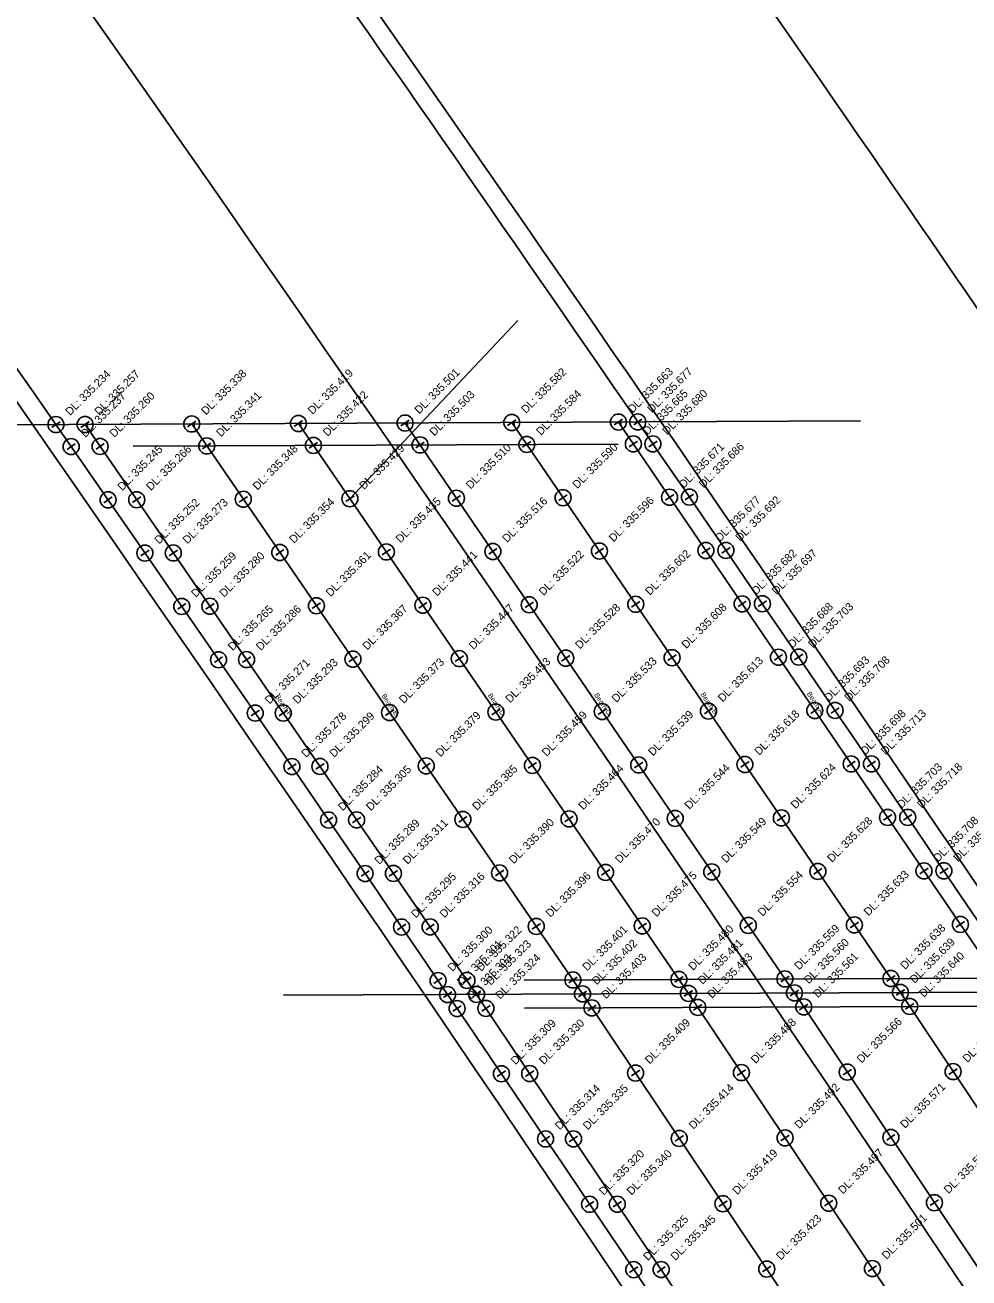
# Model space of a CAD drawing. Extents: x 1524497 to 1524592, y 1103688 to 1103812.
# Drawn here: x 1524518.53 to 1524542.12, y 1103749.84 to 1103781.14 of the extents above; entities that cross this region are included whole.
import ezdxf

# ---------------------------------------------------------------- set-up
doc = ezdxf.new("R2010")
doc.units = 0
doc.layers.add('Level 1', color=7, linetype='Continuous')

msp = doc.modelspace()

# ---------------------------------------------------------------- linework, layer by layer
at = {"layer": 'Level 1'}
for p, q in [((1524526.65, 1103769.309), (1524530.852, 1103773.763)), ((1524539.408, 1103771.253), (1524515.175, 1103771.141)), ((1524519.407, 1103771.231), (1524519.202, 1103771.089)), ((1524519.929, 1103771.092), (1524520.135, 1103771.234)), ((1524520.032, 1103771.163), (1524529.816, 1103756.923)), ((1524522.595, 1103771.105), (1524522.801, 1103771.246)), ((1524522.698, 1103771.176), (1524532.464, 1103756.935)), ((1524525.261, 1103771.117), (1524525.467, 1103771.259)), ((1524525.364, 1103771.188), (1524535.113, 1103756.948)), ((1524527.927, 1103771.13), (1524528.133, 1103771.271)), ((1524528.03, 1103771.2), (1524537.761, 1103756.96)), ((1524530.593, 1103771.142), (1524530.799, 1103771.283)), ((1524530.696, 1103771.213), (1524540.409, 1103756.972)), ((1524533.259, 1103771.155), (1524533.465, 1103771.295)), ((1524533.362, 1103771.225), (1524543.057, 1103756.984)), ((1524533.949, 1103771.298), (1524533.743, 1103771.156)), ((1524519.788, 1103770.683), (1524519.582, 1103770.54)), ((1524520.306, 1103770.544), (1524520.512, 1103770.686)), ((1524533.352, 1103770.675), (1524521.236, 1103770.619)), ((1524522.971, 1103770.557), (1524523.177, 1103770.698)), ((1524525.636, 1103770.569), (1524525.843, 1103770.71)), ((1524528.302, 1103770.581), (1524528.508, 1103770.723)), ((1524530.967, 1103770.594), (1524531.173, 1103770.735)), ((1524533.632, 1103770.606), (1524533.839, 1103770.747)), ((1524534.326, 1103770.75), (1524534.12, 1103770.608)), ((1524520.71, 1103769.352), (1524520.505, 1103769.21)), ((1524521.22, 1103769.214), (1524521.426, 1103769.355)), ((1524523.884, 1103769.226), (1524524.09, 1103769.368)), ((1524526.547, 1103769.239), (1524526.754, 1103769.38)), ((1524529.211, 1103769.251), (1524529.417, 1103769.392)), ((1524531.874, 1103769.263), (1524532.081, 1103769.404)), ((1524534.538, 1103769.276), (1524534.744, 1103769.416)), ((1524535.239, 1103769.419), (1524535.033, 1103769.278)), ((1524521.632, 1103768.021), (1524521.426, 1103767.879)), ((1524522.135, 1103767.882), (1524522.341, 1103768.024)), ((1524524.797, 1103767.895), (1524525.003, 1103768.036)), ((1524527.459, 1103767.907), (1524527.665, 1103768.048)), ((1524530.12, 1103767.92), (1524530.327, 1103768.061)), ((1524532.782, 1103767.932), (1524532.989, 1103768.073)), ((1524535.444, 1103767.944), (1524535.651, 1103768.085)), ((1524536.152, 1103768.088), (1524535.945, 1103767.946)), ((1524523.05, 1103766.55), (1524523.256, 1103766.692)), ((1524525.71, 1103766.563), (1524525.917, 1103766.704)), ((1524528.371, 1103766.575), (1524528.577, 1103766.716)), ((1524531.031, 1103766.587), (1524531.237, 1103766.728)), ((1524533.691, 1103766.6), (1524533.897, 1103766.741)), ((1524536.351, 1103766.612), (1524536.558, 1103766.753)), ((1524537.063, 1103766.755), (1524536.856, 1103766.614)), ((1524522.552, 1103766.689), (1524522.347, 1103766.547)), ((1524523.471, 1103765.356), (1524523.265, 1103765.214)), ((1524523.966, 1103765.217), (1524524.172, 1103765.359)), ((1524526.625, 1103765.23), (1524526.831, 1103765.371)), ((1524529.283, 1103765.242), (1524529.489, 1103765.383)), ((1524531.942, 1103765.254), (1524532.148, 1103765.395)), ((1524534.6, 1103765.267), (1524534.807, 1103765.408)), ((1524537.259, 1103765.279), (1524537.465, 1103765.42)), ((1524537.973, 1103765.422), (1524537.766, 1103765.281)), ((1524524.389, 1103764.022), (1524524.183, 1103763.88)), ((1524524.883, 1103763.883), (1524525.089, 1103764.025)), ((1524527.539, 1103763.896), (1524527.746, 1103764.037)), ((1524530.196, 1103763.908), (1524530.403, 1103764.049)), ((1524532.853, 1103763.92), (1524533.06, 1103764.061)), ((1524535.51, 1103763.933), (1524535.716, 1103764.074)), ((1524538.167, 1103763.945), (1524538.373, 1103764.086)), ((1524538.881, 1103764.088), (1524538.675, 1103763.948)), ((1524525.306, 1103762.687), (1524525.099, 1103762.545)), ((1524525.8, 1103762.549), (1524526.006, 1103762.69)), ((1524528.455, 1103762.561), (1524528.661, 1103762.702)), ((1524531.11, 1103762.573), (1524531.316, 1103762.715)), ((1524533.765, 1103762.586), (1524533.972, 1103762.727)), ((1524536.42, 1103762.598), (1524536.627, 1103762.739)), ((1524539.075, 1103762.61), (1524539.282, 1103762.751)), ((1524539.789, 1103762.753), (1524539.582, 1103762.613)), ((1524532.024, 1103761.238), (1524532.231, 1103761.379)), ((1524534.678, 1103761.25), (1524534.884, 1103761.391)), ((1524537.331, 1103761.262), (1524537.538, 1103761.403)), ((1524539.985, 1103761.275), (1524540.191, 1103761.415)), ((1524540.695, 1103761.418), (1524540.488, 1103761.277)), ((1524526.221, 1103761.351), (1524526.015, 1103761.21)), ((1524526.717, 1103761.213), (1524526.923, 1103761.355)), ((1524529.371, 1103761.225), (1524529.577, 1103761.367)), ((1524527.135, 1103760.015), (1524526.929, 1103759.874)), ((1524527.636, 1103759.877), (1524527.842, 1103760.018)), ((1524530.287, 1103759.889), (1524530.494, 1103760.03)), ((1524532.939, 1103759.901), (1524533.145, 1103760.043)), ((1524535.591, 1103759.914), (1524535.797, 1103760.055)), ((1524538.243, 1103759.926), (1524538.449, 1103760.067)), ((1524540.894, 1103759.938), (1524541.101, 1103760.079)), ((1524541.6, 1103760.081), (1524541.393, 1103759.941)), ((1524528.048, 1103758.677), (1524527.841, 1103758.536)), ((1524528.554, 1103758.539), (1524528.76, 1103758.681)), ((1524531.204, 1103758.552), (1524531.411, 1103758.693)), ((1524533.855, 1103758.564), (1524534.061, 1103758.705)), ((1524536.505, 1103758.576), (1524536.711, 1103758.717)), ((1524539.155, 1103758.589), (1524539.361, 1103758.73)), ((1524541.805, 1103758.601), (1524542.011, 1103758.742)), ((1524528.959, 1103757.339), (1524528.752, 1103757.198)), ((1524529.474, 1103757.201), (1524529.68, 1103757.343)), ((1524543.043, 1103757.334), (1524531.008, 1103757.279)), ((1524532.122, 1103757.214), (1524532.328, 1103757.355)), ((1524534.771, 1103757.226), (1524534.977, 1103757.367)), ((1524537.419, 1103757.238), (1524537.625, 1103757.379)), ((1524540.067, 1103757.251), (1524540.274, 1103757.392)), ((1524549.062, 1103757.012), (1524524.992, 1103756.901)), ((1524529.197, 1103756.99), (1524528.99, 1103756.85)), ((1524529.197, 1103756.99), (1524528.99, 1103756.85)), ((1524529.713, 1103756.852), (1524529.919, 1103756.994)), ((1524529.713, 1103756.854), (1524529.92, 1103756.993)), ((1524532.361, 1103756.865), (1524532.568, 1103757.006)), ((1524532.361, 1103756.866), (1524532.568, 1103757.005)), ((1524535.009, 1103756.877), (1524535.216, 1103757.018)), ((1524535.009, 1103756.878), (1524535.216, 1103757.017)), ((1524537.657, 1103756.889), (1524537.864, 1103757.03)), ((1524537.657, 1103756.891), (1524537.865, 1103757.029)), ((1524540.305, 1103756.902), (1524540.512, 1103757.043)), ((1524540.305, 1103756.903), (1524540.513, 1103757.041)), ((1524529.816, 1103756.923), (1524541.257, 1103739.876)), ((1524532.464, 1103756.935), (1524543.885, 1103739.888)), ((1524535.113, 1103756.948), (1524546.512, 1103739.9)), ((1524537.761, 1103756.96), (1524549.14, 1103739.912)), ((1524537.889, 1103756.542), (1524538.097, 1103756.68)), ((1524540.409, 1103756.972), (1524551.767, 1103739.924)), ((1524540.537, 1103756.554), (1524540.745, 1103756.693)), ((1524529.434, 1103756.641), (1524529.227, 1103756.501)), ((1524529.947, 1103756.505), (1524530.154, 1103756.644)), ((1524543.047, 1103756.634), (1524531.012, 1103756.579)), ((1524532.594, 1103756.517), (1524532.802, 1103756.656)), ((1524535.242, 1103756.529), (1524535.45, 1103756.668)), ((1524530.54, 1103755.012), (1524530.333, 1103754.871)), ((1524531.04, 1103754.875), (1524531.248, 1103755.014)), ((1524533.686, 1103754.887), (1524533.894, 1103755.027)), ((1524536.332, 1103754.9), (1524536.539, 1103755.039)), ((1524538.977, 1103754.912), (1524539.185, 1103755.051)), ((1524541.623, 1103754.924), (1524541.831, 1103755.063)), ((1524531.644, 1103753.381), (1524531.437, 1103753.241)), ((1524532.135, 1103753.244), (1524532.342, 1103753.384)), ((1524534.778, 1103753.257), (1524534.986, 1103753.396)), ((1524537.422, 1103753.269), (1524537.63, 1103753.408)), ((1524540.066, 1103753.281), (1524540.273, 1103753.42)), ((1524532.747, 1103751.749), (1524532.54, 1103751.609)), ((1524533.23, 1103751.613), (1524533.438, 1103751.752)), ((1524535.872, 1103751.625), (1524536.079, 1103751.764)), ((1524538.513, 1103751.637), (1524538.721, 1103751.776)), ((1524541.155, 1103751.649), (1524541.363, 1103751.788)), ((1524533.848, 1103750.116), (1524533.64, 1103749.976)), ((1524534.326, 1103749.979), (1524534.534, 1103750.119)), ((1524536.966, 1103749.992), (1524537.173, 1103750.131)), ((1524539.605, 1103750.004), (1524539.813, 1103750.143))]:
    msp.add_line(p, q, dxfattribs=at)
for points in [[(1524520.094, 1103771.074), (1524520.084, 1103771.199), (1524520.032, 1103771.163)], [(1524522.76, 1103771.086), (1524522.75, 1103771.211), (1524522.698, 1103771.176)], [(1524525.425, 1103771.099), (1524525.416, 1103771.223), (1524525.364, 1103771.188)], [(1524528.091, 1103771.111), (1524528.082, 1103771.236), (1524528.03, 1103771.2)], [(1524530.757, 1103771.123), (1524530.748, 1103771.248), (1524530.696, 1103771.213)], [(1524533.423, 1103771.135), (1524533.414, 1103771.26), (1524533.362, 1103771.225)], [(1524537.821, 1103756.87), (1524537.813, 1103756.995), (1524537.761, 1103756.96)], [(1524540.469, 1103756.882), (1524540.461, 1103757.007), (1524540.409, 1103756.972)], [(1524529.877, 1103756.833), (1524529.868, 1103756.958), (1524529.816, 1103756.923)], [(1524532.525, 1103756.846), (1524532.516, 1103756.97), (1524532.464, 1103756.935)], [(1524535.173, 1103756.858), (1524535.164, 1103756.982), (1524535.113, 1103756.948)]]:
    msp.add_lwpolyline(points, dxfattribs=at)
for centre in [(1524525.364, 1103771.188), (1524528.03, 1103771.2), (1524530.696, 1103771.213), (1524533.362, 1103771.225), (1524533.846, 1103771.227), (1524519.304, 1103771.16), (1524520.032, 1103771.163), (1524522.698, 1103771.176), (1524519.685, 1103770.612), (1524520.409, 1103770.615), (1524523.074, 1103770.627), (1524525.74, 1103770.64), (1524528.405, 1103770.652), (1524531.07, 1103770.664), (1524533.735, 1103770.677), (1524534.223, 1103770.679), (1524526.65, 1103769.309), (1524529.314, 1103769.321), (1524531.978, 1103769.334), (1524534.641, 1103769.346), (1524535.136, 1103769.348), (1524520.608, 1103769.281), (1524521.323, 1103769.284), (1524523.987, 1103769.297), (1524521.529, 1103767.95), (1524522.238, 1103767.953), (1524524.9, 1103767.965), (1524527.562, 1103767.978), (1524530.224, 1103767.99), (1524532.886, 1103768.002), (1524535.547, 1103768.015), (1524536.049, 1103768.017), (1524522.449, 1103766.618), (1524523.153, 1103766.621), (1524525.814, 1103766.633), (1524528.474, 1103766.646), (1524531.134, 1103766.658), (1524533.794, 1103766.67), (1524536.454, 1103766.682), (1524536.96, 1103766.685), (1524523.368, 1103765.285), (1524524.069, 1103765.288), (1524526.728, 1103765.3), (1524529.386, 1103765.313), (1524532.045, 1103765.325), (1524534.703, 1103765.337), (1524537.362, 1103765.349), (1524537.869, 1103765.352), (1524532.956, 1103763.991), (1524535.613, 1103764.003), (1524538.27, 1103764.016), (1524538.778, 1103764.018), (1524524.286, 1103763.951), (1524524.986, 1103763.954), (1524527.643, 1103763.966), (1524530.299, 1103763.979), (1524525.203, 1103762.616), (1524525.903, 1103762.619), (1524528.558, 1103762.632), (1524531.213, 1103762.644), (1524533.868, 1103762.656), (1524536.523, 1103762.668), (1524539.179, 1103762.681), (1524539.685, 1103762.683), (1524526.118, 1103761.281), (1524526.82, 1103761.284), (1524529.474, 1103761.296), (1524532.127, 1103761.308), (1524534.781, 1103761.321), (1524537.434, 1103761.333), (1524540.088, 1103761.345), (1524540.591, 1103761.347), (1524527.032, 1103759.944), (1524527.739, 1103759.947), (1524530.39, 1103759.96), (1524533.042, 1103759.972), (1524535.694, 1103759.984), (1524538.346, 1103759.996), (1524540.998, 1103760.009), (1524541.496, 1103760.011), (1524541.908, 1103758.671), (1524527.944, 1103758.607), (1524528.657, 1103758.61), (1524531.308, 1103758.622), (1524533.958, 1103758.635), (1524536.608, 1103758.647), (1524539.258, 1103758.659), (1524528.856, 1103757.269), (1524529.577, 1103757.272), (1524532.225, 1103757.284), (1524534.874, 1103757.297), (1524537.522, 1103757.309), (1524540.171, 1103757.321), (1524529.093, 1103756.92), (1524529.093, 1103756.92), (1524529.816, 1103756.923), (1524529.816, 1103756.923), (1524532.464, 1103756.935), (1524532.464, 1103756.935), (1524535.113, 1103756.948), (1524535.113, 1103756.948), (1524537.761, 1103756.96), (1524537.761, 1103756.96), (1524540.409, 1103756.972), (1524540.409, 1103756.972), (1524529.33, 1103756.571), (1524530.051, 1103756.574), (1524532.698, 1103756.587), (1524535.346, 1103756.599), (1524537.993, 1103756.611), (1524540.641, 1103756.623), (1524530.437, 1103754.942), (1524531.144, 1103754.945), (1524533.79, 1103754.957), (1524536.435, 1103754.969), (1524539.081, 1103754.982), (1524541.727, 1103754.994), (1524540.17, 1103753.351), (1524531.541, 1103753.311), (1524532.239, 1103753.314), (1524534.882, 1103753.326), (1524537.526, 1103753.339), (1524532.643, 1103751.679), (1524533.334, 1103751.682), (1524535.975, 1103751.694), (1524538.617, 1103751.707), (1524541.259, 1103751.719), (1524533.744, 1103750.046), (1524534.43, 1103750.049), (1524537.069, 1103750.061), (1524539.709, 1103750.073)]:
    msp.add_circle(centre, 0.2, dxfattribs=at)
for radius in [1750, 1750, 1750, 1750, 1750, 1750, 1750, 1750, 1741.4, 1741.4, 1741.4, 1741.4, 1741.4, 1741.4, 1741.4, 1741.4, 1741.88, 1741.88, 1741.88, 1741.88, 1741.88, 1741.88, 1741.88, 1741.88, 1736, 1736, 1736, 1736, 1736, 1736, 1736, 1736, 1729.4, 1729.4, 1729.4, 1729.4, 1729.4, 1729.4, 1729.4, 1729.4, 1728.92, 1728.92, 1728.92, 1728.92, 1728.92, 1728.92, 1728.92, 1728.92]:
    msp.add_arc((1523099.068, 1102784.371), radius, 33.735131, 35.977852, dxfattribs=at)

# ---------------------------------------------------------------- texts
for s, height, rotation, p in [('DL: 335.234', 0.2, 45, (1524519.658, 1103771.372)), ('DL: 335.257', 0.2, 45, (1524520.386, 1103771.375)), ('DL: 335.338', 0.2, 45, (1524523.052, 1103771.388)), ('DL: 335.419', 0.2, 45, (1524525.718, 1103771.4)), ('DL: 335.501', 0.2, 45, (1524528.384, 1103771.412)), ('DL: 335.582', 0.2, 45, (1524531.05, 1103771.425)), ('DL: 335.663', 0.2, 45, (1524533.716, 1103771.437)), ('DL: 335.677', 0.2, 45, (1524534.2, 1103771.439)), ('DL: 335.584', 0.2, 45, (1524531.424, 1103770.876)), ('DL: 335.665', 0.2, 45, (1524534.089, 1103770.889)), ('DL: 335.680', 0.2, 45, (1524534.576, 1103770.891)), ('DL: 335.237', 0.2, 45, (1524520.039, 1103770.824)), ('DL: 335.260', 0.2, 45, (1524520.763, 1103770.827)), ('DL: 335.341', 0.2, 45, (1524523.428, 1103770.839)), ('DL: 335.422', 0.2, 45, (1524526.093, 1103770.852)), ('DL: 335.503', 0.2, 45, (1524528.758, 1103770.864)), ('DL: 335.245', 0.2, 45, (1524520.961, 1103769.493)), ('DL: 335.266', 0.2, 45, (1524521.677, 1103769.497)), ('DL: 335.348', 0.2, 45, (1524524.34, 1103769.509)), ('DL: 335.429', 0.2, 45, (1524527.004, 1103769.521)), ('DL: 335.510', 0.2, 45, (1524529.668, 1103769.534)), ('DL: 335.590', 0.2, 45, (1524532.331, 1103769.546)), ('DL: 335.671', 0.2, 45, (1524534.995, 1103769.558)), ('DL: 335.686', 0.2, 45, (1524535.49, 1103769.561)), ('DL: 335.252', 0.2, 45, (1524521.883, 1103768.162)), ('DL: 335.273', 0.2, 45, (1524522.592, 1103768.165)), ('DL: 335.354', 0.2, 45, (1524525.253, 1103768.178)), ('DL: 335.435', 0.2, 45, (1524527.915, 1103768.19)), ('DL: 335.516', 0.2, 45, (1524530.577, 1103768.202)), ('DL: 335.596', 0.2, 45, (1524533.239, 1103768.215)), ('DL: 335.677', 0.2, 45, (1524535.901, 1103768.227)), ('DL: 335.692', 0.2, 45, (1524536.402, 1103768.229)), ('DL: 335.259', 0.2, 45, (1524522.803, 1103766.83)), ('DL: 335.280', 0.2, 45, (1524523.507, 1103766.833)), ('DL: 335.361', 0.2, 45, (1524526.167, 1103766.845)), ('DL: 335.441', 0.2, 45, (1524528.827, 1103766.858)), ('DL: 335.522', 0.2, 45, (1524531.488, 1103766.87)), ('DL: 335.602', 0.2, 45, (1524534.148, 1103766.882)), ('DL: 335.682', 0.2, 45, (1524536.808, 1103766.895)), ('DL: 335.697', 0.2, 45, (1524537.313, 1103766.897)), ('DL: 335.608', 0.2, 45, (1524535.057, 1103765.549)), ('DL: 335.688', 0.2, 45, (1524537.715, 1103765.562)), ('DL: 335.703', 0.2, 45, (1524538.223, 1103765.564)), ('DL: 335.265', 0.2, 45, (1524523.722, 1103765.497)), ('DL: 335.286', 0.2, 45, (1524524.423, 1103765.5)), ('DL: 335.367', 0.2, 45, (1524527.081, 1103765.512)), ('DL: 335.447', 0.2, 45, (1524529.74, 1103765.525)), ('DL: 335.528', 0.2, 45, (1524532.398, 1103765.537)), ('DL: 335.271', 0.2, 45, (1524524.64, 1103764.163)), ('DL: 335.293', 0.2, 45, (1524525.339, 1103764.166)), ('DL: 335.373', 0.2, 45, (1524527.996, 1103764.178)), ('DL: 335.453', 0.2, 45, (1524530.653, 1103764.191)), ('DL: 335.533', 0.2, 45, (1524533.31, 1103764.203)), ('DL: 335.613', 0.2, 45, (1524535.967, 1103764.215)), ('DL: 335.693', 0.2, 45, (1524538.624, 1103764.228)), ('DL: 335.708', 0.2, 45, (1524539.132, 1103764.23)), ('Beam F', 0.125, 304.492, (1524524.778, 1103764.366)), ('Beam E', 0.125, 304.443, (1524527.434, 1103764.381)), ('Beam D', 0.125, 304.3938, (1524530.091, 1103764.394)), ('Beam C', 0.125, 304.3446, (1524532.748, 1103764.406)), ('Beam B', 0.125, 304.2954, (1524535.406, 1103764.418)), ('Beam A', 0.125, 304.2461, (1524538.062, 1103764.433)), ('DL: 335.278', 0.2, 45, (1524525.556, 1103762.828)), ('DL: 335.299', 0.2, 45, (1524526.256, 1103762.831)), ('DL: 335.379', 0.2, 45, (1524528.912, 1103762.844)), ('DL: 335.459', 0.2, 45, (1524531.567, 1103762.856)), ('DL: 335.539', 0.2, 45, (1524534.222, 1103762.868)), ('DL: 335.618', 0.2, 45, (1524536.877, 1103762.881)), ('DL: 335.698', 0.2, 45, (1524539.532, 1103762.893)), ('DL: 335.713', 0.2, 45, (1524540.039, 1103762.895)), ('DL: 335.284', 0.2, 45, (1524526.471, 1103761.493)), ('DL: 335.305', 0.2, 45, (1524527.174, 1103761.496)), ('DL: 335.385', 0.2, 45, (1524529.827, 1103761.508)), ('DL: 335.464', 0.2, 45, (1524532.481, 1103761.52)), ('DL: 335.544', 0.2, 45, (1524535.134, 1103761.533)), ('DL: 335.624', 0.2, 45, (1524537.788, 1103761.545)), ('DL: 335.703', 0.2, 45, (1524540.441, 1103761.557)), ('DL: 335.718', 0.2, 45, (1524540.945, 1103761.56)), ('DL: 335.289', 0.2, 45, (1524527.385, 1103760.156)), ('DL: 335.311', 0.2, 45, (1524528.092, 1103760.16)), ('DL: 335.390', 0.2, 45, (1524530.744, 1103760.172)), ('DL: 335.470', 0.2, 45, (1524533.396, 1103760.184)), ('DL: 335.549', 0.2, 45, (1524536.048, 1103760.196)), ('DL: 335.628', 0.2, 45, (1524538.699, 1103760.209)), ('DL: 335.708', 0.2, 45, (1524541.351, 1103760.221)), ('DL: 335.722', 0.2, 45, (1524541.85, 1103760.223)), ('DL: 335.295', 0.2, 45, (1524528.298, 1103758.819)), ('DL: 335.316', 0.2, 45, (1524529.011, 1103758.822)), ('DL: 335.396', 0.2, 45, (1524531.661, 1103758.835)), ('DL: 335.475', 0.2, 45, (1524534.311, 1103758.847)), ('DL: 335.554', 0.2, 45, (1524536.961, 1103758.859)), ('DL: 335.633', 0.2, 45, (1524539.612, 1103758.871)), ('DL: 335.300', 0.2, 45, (1524529.209, 1103757.481)), ('DL: 335.322', 0.2, 45, (1524529.93, 1103757.484)), ('DL: 335.401', 0.2, 45, (1524532.579, 1103757.496)), ('DL: 335.480', 0.2, 45, (1524535.227, 1103757.509)), ('DL: 335.559', 0.2, 45, (1524537.876, 1103757.521)), ('DL: 335.638', 0.2, 45, (1524540.524, 1103757.533)), ('DL: 335.301', 0.2, 45, (1524529.447, 1103757.132)), ('DL: 335.301', 0.2, 45, (1524529.447, 1103757.132)), ('DL: 335.323', 0.2, 45, (1524530.17, 1103757.135)), ('DL: 335.323', 0.2, 45, (1524530.17, 1103757.135)), ('DL: 335.402', 0.2, 45, (1524532.818, 1103757.148)), ('DL: 335.402', 0.2, 45, (1524532.818, 1103757.148)), ('DL: 335.481', 0.2, 45, (1524535.466, 1103757.16)), ('DL: 335.481', 0.2, 45, (1524535.466, 1103757.16)), ('DL: 335.560', 0.2, 45, (1524538.114, 1103757.172)), ('DL: 335.560', 0.2, 45, (1524538.114, 1103757.172)), ('DL: 335.639', 0.2, 45, (1524540.762, 1103757.184)), ('DL: 335.639', 0.2, 45, (1524540.762, 1103757.184)), ('DL: 335.324', 0.2, 45, (1524530.404, 1103756.786)), ('DL: 335.403', 0.2, 45, (1524533.052, 1103756.799)), ('DL: 335.483', 0.2, 45, (1524535.699, 1103756.811)), ('DL: 335.561', 0.2, 45, (1524538.347, 1103756.823)), ('DL: 335.640', 0.2, 45, (1524540.995, 1103756.835)), ('DL: 335.303', 0.2, 45, (1524529.684, 1103756.783)), ('DL: 335.645', 0.2, 45, (1524542.08, 1103755.206)), ('DL: 335.309', 0.2, 45, (1524530.79, 1103755.154)), ('DL: 335.330', 0.2, 45, (1524531.498, 1103755.157)), ('DL: 335.409', 0.2, 45, (1524534.143, 1103755.169)), ('DL: 335.488', 0.2, 45, (1524536.789, 1103755.181)), ('DL: 335.566', 0.2, 45, (1524539.435, 1103755.194)), ('DL: 335.314', 0.2, 45, (1524531.895, 1103753.523)), ('DL: 335.335', 0.2, 45, (1524532.592, 1103753.526)), ('DL: 335.414', 0.2, 45, (1524535.236, 1103753.538)), ('DL: 335.492', 0.2, 45, (1524537.879, 1103753.551)), ('DL: 335.571', 0.2, 45, (1524540.523, 1103753.563)), ('DL: 335.320', 0.2, 45, (1524532.997, 1103751.891)), ('DL: 335.340', 0.2, 45, (1524533.687, 1103751.894)), ('DL: 335.419', 0.2, 45, (1524536.329, 1103751.907)), ('DL: 335.497', 0.2, 45, (1524538.971, 1103751.919)), ('DL: 335.575', 0.2, 45, (1524541.612, 1103751.931)), ('DL: 335.325', 0.2, 45, (1524534.098, 1103750.258)), ('DL: 335.345', 0.2, 45, (1524534.783, 1103750.261)), ('DL: 335.423', 0.2, 45, (1524537.423, 1103750.273)), ('DL: 335.501', 0.2, 45, (1524540.063, 1103750.286))]:
    msp.add_text(s, height=height, rotation=rotation, dxfattribs=at).set_placement(p)

doc.saveas('drawing.dxf')
